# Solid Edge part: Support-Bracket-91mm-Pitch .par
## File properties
Author: davee
Template: Normal.par
Last saved by: davee
Revision: 4
Application: Solid Edge
Accuracy: 0.990
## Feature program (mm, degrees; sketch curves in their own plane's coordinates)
body "unnamed Body 1"
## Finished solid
Body 1: solid body, 355 faces, 812 edges, 462 vertices.
  Faces by surface: cylinder 134, plane 115, torus 38, spline 24, cone 18, sphere 16, swept 6, spun 4
  Edges by curve: line 410, circle 266, ellipse 66, intersection 30, spline 21, curve on surface 19
Bounding box of the edges (mm; curved faces can reach further): 130.500 x 90.500 x 75.000, from (-65.25, -40, -10) to (65.25, 50.5, 65).
Cylindrical faces by radius (mm): R0.5 x2, R0.75 x27, R0.8 x6, R1 x64, R1.1 x2, R1.5 x5, R1.75 x2, R2 x3, R2.26 x2, R2.75 x2, R3 x3, R3.2 x2, R3.5 x2, R5 x2, R6 x8, R12 x2
Conical faces (half-angle, radius in mm at the cone's reference point): 1 deg R1.75 x2, 1 deg R2.4 x2, 3 deg R1.5 x8, 3 deg R3.7722 x1, 3 deg R3.7827 x1, 45 deg R1.1 x2, 45 deg R2 x2
Toroidal faces (ring radius, tube radius in mm): R0.75 r0.75 x2, R1.25 r0.75 x2, R2 r1 x6, R2.25 r0.75 x2, R2.2592 r0.8 x8, R2.45 r0.75 x2, R3.013 r0.8 x1, R3.0235 r0.8 x1, R3.5 r2 x2, R5.25 r0.75 x2, R5.3762 r1 x1, R5.3868 r1 x1, R7 r1 x6, R7 r2 x2
Spherical faces by radius (mm): R1 x14, R1.5 x2
Planar faces by outward normal: +x 9, +y 22, +z 9, -x 10, -y 20, -z 17, oblique 28
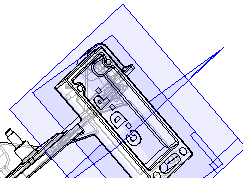
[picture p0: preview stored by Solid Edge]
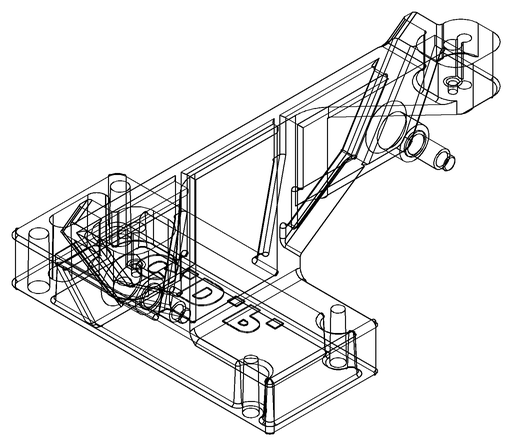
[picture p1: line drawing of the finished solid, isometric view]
